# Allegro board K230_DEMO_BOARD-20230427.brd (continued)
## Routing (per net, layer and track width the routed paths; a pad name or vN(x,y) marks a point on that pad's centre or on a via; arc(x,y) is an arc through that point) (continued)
MMC1_D0: length 64.6
  TOP w0.127: v1(31.37,102.49) 27.81,102.49 27.43,102.11 25.78,102.11 24.89,101.22 24.89,99.57 R123.1 ; U4.7 67.62,83.89 v1(68.33,83.19)
  ART06 w0.127: v1(68.33,83.19) 69.09,83.95 69.09,89.28 66.1,92.27 62.8,92.27 61.79,93.28 60.52,93.28 59.05,94.74 51.94,94.74 46.48,100.2 34.54,100.2 32.89,101.85 32,101.85 v1(31.37,102.49)
  BOTTOM w0.127: R189.2 v1(68.33,83.19) 67.82,83.69 U23.2
MMC1_D1: length 66.7
  TOP w0.127: v1(68.33,81.92) 67.45,82.79 U4.8 ; v1(32.64,101.35) 32.13,100.84 29.59,100.84 R124.1
  ART06 w0.127: v1(32.64,101.35) 32.77,101.35 34.29,99.82 46.23,99.82 51.44,94.61 51.44,93.92 51.69,93.66 52.66,93.66 52.81,93.81 52.81,94.09 52.96,94.23 53.17,94.23 53.32,94.09 53.32,93.81 53.47,93.66 53.68,93.66 53.83,93.81 53.83,94.09 53.98,94.23 54.19,94.23 54.34,94.09 54.34,93.81 54.49,93.66 54.7,93.66 54.84,93.81 54.84,94.09 54.99,94.23 55.2,94.23 55.35,94.09 55.35,93.81 55.5,93.66 55.71,93.66 55.86,93.81 55.86,94.09 56.01,94.23 56.22,94.23 56.37,94.09 56.37,93.81 56.52,93.66 57.85,93.66 58.17,93.34 58.38,93.34 59,93.96 59.21,93.96 59.35,93.81 59.35,93.6 58.74,92.98 58.74,92.77 59.6,91.91 64.75,91.91 64.9,91.76 64.9,91.46 65.04,91.31 65.25,91.31 65.4,91.46 65.4,91.76 65.55,91.91 65.83,91.91 68.71,89.03 68.71,84.84 67.82,83.95 67.82,82.42 v1(68.33,81.92)
  BOTTOM w0.127: R190.2 v1(68.33,81.92) 67.82,81.41 U23.3
MMC1_D2: length 66.5
  TOP w0.127: R125.1 25.91,99.44 25.91,100.84 26.16,101.09 27.56,101.09 28.45,101.98 32,101.98 v1(32.51,102.49) ; v1(68.46,90.81) 68.13,90.49 U4.1
  ART06 w0.127: v1(68.46,90.81) 66.56,92.71 62.87,92.71 61.98,93.6 60.96,93.6 58.29,96.27 52.45,96.27 48.13,100.58 46.24,100.58 46.09,100.73 46.09,101.07 45.95,101.22 45.73,101.22 45.59,101.07 45.59,100.73 45.44,100.58 45.23,100.58 45.08,100.73 45.08,101.07 44.93,101.22 44.72,101.22 44.57,101.07 44.57,100.73 44.42,100.58 44.14,100.58 43.99,100.73 43.99,101.07 43.85,101.22 43.63,101.22 43.49,101.07 43.49,100.73 43.34,100.58 43.13,100.58 42.98,100.73 42.98,101.07 42.83,101.22 42.62,101.22 42.47,101.07 42.47,100.73 42.32,100.58 42.11,100.58 41.96,100.73 41.96,101.07 41.81,101.22 41.6,101.22 41.45,101.07 41.45,100.73 41.31,100.58 41.09,100.58 40.95,100.73 40.95,101.07 40.8,101.22 40.59,101.22 40.44,101.07 40.44,100.73 40.29,100.58 40.08,100.58 39.93,100.73 39.93,101.07 39.78,101.22 39.57,101.22 39.42,101.07 39.42,100.73 39.27,100.58 39.06,100.58 38.91,100.73 38.91,101.07 38.77,101.22 38.55,101.22 38.41,101.07 38.41,100.73 38.26,100.58 38.05,100.58 37.9,100.73 37.9,101.07 37.75,101.22 37.54,101.22 37.39,101.07 37.39,100.73 37.24,100.58 37.03,100.58 36.88,100.73 36.88,101.07 36.73,101.22 36.52,101.22 36.37,101.07 36.37,100.73 36.23,100.58 36.01,100.58 35.87,100.73 35.87,101.32 35.72,101.47 35.51,101.47 35.36,101.32 35.36,100.73 35.22,100.6 34.79,100.6 32.89,102.49 v1(32.51,102.49)
  BOTTOM w0.127: U24.2 67.96,91.31 v1(68.46,90.81) R191.2
MMC1_D3: length 66.1
  TOP w0.127: U4.2 67.33,89.39 v1(67.82,88.9) ; v1(31.37,101.35) 28.96,101.35 R126.1
  ART06 w0.127: v1(67.82,88.9) 67.08,89.64 66.87,89.64 66.44,89.22 66.23,89.22 66.08,89.37 66.08,89.58 66.51,90 66.51,90.21 66.04,90.68 64.26,90.68 63.37,91.57 59.44,91.57 57.78,93.22 50.8,93.22 50.51,93.51 50.51,93.72 51,94.21 51,94.42 50.85,94.57 50.64,94.57 50.15,94.08 49.94,94.08 49.79,94.23 49.79,94.44 50.28,94.93 50.28,95.14 50.13,95.29 49.92,95.29 49.43,94.8 49.22,94.8 49.07,94.95 49.07,95.16 49.56,95.64 49.56,95.85 49.41,96 49.2,96 48.71,95.52 48.5,95.52 48.35,95.66 48.35,95.88 48.84,96.36 48.84,96.57 48.69,96.72 48.48,96.72 47.99,96.23 47.78,96.23 47.63,96.38 47.63,96.59 48.12,97.08 48.12,97.29 47.97,97.44 47.76,97.44 47.27,96.95 47.06,96.95 46.92,97.1 46.92,97.31 47.4,97.8 47.4,98.01 47.25,98.16 47.04,98.16 46.56,97.67 46.35,97.67 46.2,97.82 46.2,98.03 46.68,98.52 46.68,98.73 46.54,98.88 46.33,98.88 45.84,98.39 45.63,98.39 45.48,98.54 45.48,98.75 45.79,99.06 45.79,99.24 45.61,99.42 45.43,99.42 45.12,99.11 44.91,99.11 44.58,99.44 34.16,99.44 32.89,100.71 32,100.71 v1(31.37,101.35)
  BOTTOM w0.127: U24.3 67.69,89.03 v1(67.82,88.9) R193.2
NC_NC: length 3.3
  TOP w0.127: R207.2 1.91,38.1
OSPI_CLK: length 43.2
  TOP w0.127: v3(29.79,94.61) 29.72,94.54 29.72,92.25 28.9,91.43 U1.K1 ; J9.14 28.89,106.36 29.46,106.93 32.26,106.93 32.64,107.31 v1(32.64,113.67)
  ART06 w0.127: v3(29.79,94.61) 29.22,95.19 29.22,96.41 29.95,97.13 29.95,109.07 30.61,109.73 30.61,113.28 30.99,113.67 v1(32.64,113.67)
OSPI_CS: length 43.9
  TOP w0.127: J9.6 23.18,118.3 25.65,115.82 25.65,111.38 26.29,110.74 27.18,110.74 v1(27.69,111.25) ; U1.J5 v2(29.22,83.26)
  ART06 w0.076: 28.24,85.6 28.24,84.24 v2(29.22,83.26)
  ART06 w0.127: v1(27.69,111.25) 27.69,108.97 28,108.65 28,98.36 27.18,97.54 27.18,88.37 28.3,87.25 28.3,86.44 28.24,86.39 28.24,85.6
OSPI_D0: length 43.3
  TOP w0.076: U1.K2 29.23,85.86 29.23,86.49
  TOP w0.127: v1(30.86,96.01) 30.35,95.5 30.35,92.44 29.23,91.32 29.23,86.49 ; v1(32,107.57) 29.08,107.57 26.99,105.47 J9.13
  ART06 w0.127: v1(30.86,96.01) 30.77,96.1 30.77,102.91 30.92,103.06 34.27,103.06 34.42,103.21 34.42,103.42 34.27,103.57 30.92,103.57 30.77,103.72 30.77,103.93 30.92,104.08 33.38,104.08 33.53,104.23 33.53,104.44 33.38,104.59 30.92,104.59 30.77,104.74 30.77,105.03 30.9,105.16 31.88,105.16 32,105.28 v1(32,107.57)
OSPI_D1: length 43.4
  TOP w0.127: J9.7 21.27,119.57 25.27,115.57 25.27,111.12 26.04,110.36 v1(28.19,110.36) ; U1.K4 v2(29.22,84.56)
  ART06 w0.076: v2(29.22,84.56) 28.98,84.56 28.7,84.84 28.7,85.98 28.83,86.11
  ART06 w0.127: 28.83,86.11 28.91,86.18 28.91,87.68 27.93,88.66 27.93,97.14 28.74,97.96 28.74,109.82 v1(28.19,110.36)
OSPI_D2: length 43.1
  TOP w0.127: U1.K5 v2(29.22,83.91) ; v1(28.19,109.35) 26.54,109.35 26.17,108.97 25.96,108.97 25.53,109.4 25.32,109.4 25.17,109.25 25.17,109.04 25.6,108.61 25.6,108.4 25.45,108.25 25.24,108.25 24.81,108.68 24.6,108.68 24.45,108.53 24.45,108.32 24.88,107.89 24.88,107.68 24.73,107.53 24.52,107.53 24.09,107.96 23.88,107.96 23.73,107.81 23.73,107.6 24.16,107.17 24.16,106.96 24,106.81 20.83,106.81 19.37,105.35 J9.9
  ART06 w0.076: 28.57,86.36 28.57,86.23 28.49,86.14 28.49,84.65 v2(29.22,83.91)
  ART06 w0.127: v1(28.19,109.35) 28.36,109.18 28.36,98.21 27.56,97.41 27.56,88.52 28.57,87.5 28.57,86.36
OSPI_D3: length 43
  TOP w0.127: v1(29.21,118.36) 28.89,118.68 J9.3 ; v1(28.71,94.61) 28.71,92.62 28.25,92.16 U1.L1
  ART06 w0.127: v1(29.21,118.36) 29.72,118.36 29.97,118.11 29.97,113.79 29.82,113.64 28.98,113.64 28.83,113.49 28.83,113.28 28.98,113.14 29.82,113.14 29.97,112.99 29.97,112.78 29.82,112.63 28.98,112.63 28.83,112.48 28.83,112.27 28.98,112.12 29.82,112.12 29.97,111.97 29.97,111.76 29.82,111.61 28.98,111.61 28.83,111.46 28.83,111.25 28.98,111.1 29.82,111.1 29.97,110.95 29.97,110.11 29.44,109.58 29.44,97.51 28.71,96.79 v1(28.71,94.61)
OSPI_D4: length 43.1
  TOP w0.076: 28.58,86.61 28.58,85.86 U1.L2
  TOP w0.127: J9.12 25.08,105.35 28.57,108.84 v1(32,108.84) ; v1(29.84,96.01) 29.21,95.38 29.21,92.71 28.58,92.08 28.58,86.61
  ART06 w0.127: v1(29.84,96.01) 30.45,96.62 30.45,108.81 31.24,109.6 31.24,112.9 31.37,113.03 31.88,113.03 32,112.9 v1(32,108.84)
OSPI_D5: length 43
  TOP w0.127: J9.5 25.08,120.62 25.23,120.48 25.76,120.48 25.91,120.33 25.91,120.12 25.76,119.97 25.23,119.97 25.08,119.82 25.08,119.61 25.23,119.46 25.76,119.46 25.91,119.31 25.91,119.1 25.76,118.95 25.23,118.95 25.08,118.8 25.08,118.59 25.23,118.44 25.76,118.44 25.91,118.3 25.91,118.08 25.76,117.94 25.23,117.94 25.08,117.79 25.08,117.03 26.16,115.95 26.16,111.76 v1(26.67,111.25) ; U1.L3 v2(27.93,85.21)
  ART06 w0.127: v2(27.93,85.21) 27.93,87.01 26.8,88.14 26.8,97.66 27.65,98.51 27.65,108.5 26.67,109.47 v1(26.67,111.25)
OSPI_D6: length 43.2
  TOP w0.127: U1.L4 v2(27.93,84.56) ; v1(26.35,108.2) 24.45,106.3 23.54,106.3 23.39,106.15 23.39,105.81 23.24,105.66 23.03,105.66 22.88,105.81 22.88,106.15 22.74,106.3 22.53,106.3 22.38,106.15 22.38,105.81 22.23,105.66 22.02,105.66 21.87,105.81 21.87,106.15 21.72,106.3 21.46,106.3 21.27,106.11 J9.10
  ART06 w0.076: v2(27.93,84.56) 27.93,84.72 27.6,85.05 27.6,85.47
  ART06 w0.127: v1(26.35,108.2) 27.05,108.2 27.28,107.98 27.28,107.77 27.13,107.62 26.31,107.62 26.16,107.47 26.16,107.26 26.31,107.11 27.13,107.11 27.28,106.96 27.28,106.75 27.13,106.61 26.31,106.61 26.16,106.46 26.16,106.25 26.31,106.1 27.13,106.1 27.28,105.95 27.28,105.74 27.13,105.59 26.31,105.59 26.16,105.44 26.16,105.23 26.31,105.08 27.13,105.08 27.28,104.93 27.28,104.72 27.13,104.57 26.31,104.57 26.16,104.42 26.16,104.21 26.31,104.07 27.13,104.07 27.28,103.92 27.28,98.78 26.41,97.91 26.41,87.93 27.6,86.74 27.6,85.47
OSPI_D7: length 43.1
  TOP w0.127: v1(26.99,112.65) J9.4 ; U1.L5 v2(27.93,83.91)
  ART06 w0.076: 27.3,85.34 27.3,84.99 27.6,84.7 27.6,84.34 27.93,84.01 v2(27.93,83.91)
  ART06 w0.127: 27.3,85.34 27.3,86.49 26.01,87.78 26.01,98.02 26.92,98.93 26.92,103.5 26.8,103.63 25.91,103.63 25.78,103.76 25.78,113.16 26.04,113.41 26.8,113.41 26.99,113.22 v1(26.99,112.65)
OSPI_DQS: length 43.2
  TOP w0.127: U1.L6 v2(27.93,83.26) ; J9.11 v1(23.18,99.82)
  ART06 w0.076: 26.94,85.58 26.94,84.44 27.14,84.24 27.39,84.24 27.59,84.04 27.59,83.6 v2(27.93,83.26)
  ART06 w0.127: 26.94,85.58 26.94,86.36 25.69,87.61 25.69,96.62 25.46,96.84 22.39,96.84 22.25,96.99 22.25,97.2 22.39,97.35 25.54,97.35 25.66,97.48 25.66,97.66 25.46,97.86 22.39,97.86 22.25,98.01 22.25,98.22 22.39,98.36 25.56,98.36 25.69,98.49 25.69,98.9 25.53,99.06 22.35,99.06 22.23,99.19 22.23,101.6 22.35,101.73 22.86,101.73 22.99,101.6 22.99,100.01 v1(23.18,99.82)
PG_CORE: length 57.3
  TOP w0.254: U17.7 33.63,19.44 v1(33.15,18.95) ; U21.7 33.63,9.91 v1(33.15,9.42) ; v1(38.61,43.31) 38.86,43.05 47.75,43.05 49.15,44.45 R151.2 49.91,45.85 49.91,48.77 50.55,49.41 U20.2
  ART06 w0.254: v1(33.15,9.42) 33.02,9.55 33.02,18.82 v1(33.15,18.95) 33.02,19.08 33.02,25.27 34.04,26.29 34.04,41.15 34.37,41.48 37.41,41.48 37.72,41.78 37.72,42.42 v1(38.61,43.31)
PW_EN: length 119.3
  TOP w0.254: v1(50.06,52.58) 50.55,52.09 U20.7 ; U27.4 64.64,50.93 v1(64.77,50.8) ; v1(54.74,27.3) 54.6,27.44 U28.4 ; v1(42.29,44.96) 41.64,45.61 U12.4
  TOP w0.381: U18.1 57.03,73.92 v1(56.39,73.28)
  ART06 w0.254: v1(42.29,44.96) 43.05,45.72 43.05,48.26 47.37,52.58 v1(50.06,52.58) 50.19,52.7 56.26,52.7 57.99,50.98 64.59,50.98 v1(64.77,50.8) 64.14,50.16 64.14,46.86 58.17,40.89 58.17,30.73 v1(54.74,27.3) 54.61,27.18 54.61,22.1 48.9,16.38 v1(48.9,7.62)
  BOTTOM w0.254: 52.7,1.91 50.16,1.91 48.9,3.17 v1(48.9,7.62) 48.9,7.87 C268.1 ; v1(50.06,52.58) 52.58,52.58 53.85,53.85 53.85,70.74 v1(56.39,73.28)
PWIN_FLASH: length 48.8
  TOP w0.127: J9.8 19.37,120.78 24.77,115.38 24.77,111 25.91,109.86 28.83,109.86 v1(29.34,110.36) ; U1.K7 v2(29.22,81.96)
  ART06 w0.127: v1(29.34,110.36) 29.08,110.11 29.08,97.66 28.22,96.8 28.22,92.91 v2(28.32,92.81)
  BOTTOM w0.127: v2(28.32,92.81) 27.81,92.3 27.81,86.49 27.94,86.36 C27.1 28.32,82.86 v2(29.22,81.96)
RTC_1V8: length 117.6
  TOP w0.254: U1.F15 v2(31.82,77.41) U1.F14
  TOP w0.305: v1(48.77,73.63) Y2.4
  TOP w0.381: v1(71.25,34.67) R150.2 69.61,37.08 64.39,37.08 59.82,41.66 46.86,41.66 45.85,40.64 ; R262.2 v1(71.25,26.8) ; 33.02,1.91 34.29,3.17 56.52,3.17 57.78,1.91 60.33,1.91 61.47,3.05 64.26,3.05 65.41,1.91
  ART06 w0.381: 65.41,1.91 66.67,3.17 68.45,3.17 70.61,5.33 70.61,26.16 v1(71.25,26.8) v1(71.25,34.67)
  BOTTOM w0.381: R62.2 51.44,3.94 52.2,3.17 56.52,3.17 57.78,1.91 60.33,1.91
  vias: v1(43.18,40.39) v1(44.32,40.39)
RTC_1V8_TI: length 42.8
  TOP w0.305: R185.2 42.93,35.18
  ART06 w0.305: v1(45.72,7.75) 45.97,8 45.97,33.02 45.34,33.66 44.07,33.66 v1(43.43,34.29)
  BOTTOM w0.305: 35.56,1.91 36.83,3.17 36.83,4.83 37.85,5.84 43.81,5.84 v1(45.72,7.75)
RTC_CLK_IN: length 20
  TOP w0.076: U1.B12 34.42,79.36 34.92,79.36
  TOP w0.127: R7.2 46.99,70.1 46.74,70.36 46.74,73.66 45.72,74.68 40.44,74.68 39.37,75.74 39.37,77.13 38.3,78.19 37.81,78.19 36.64,79.36 34.92,79.36
RTC_CLK_OUT: length 19.8
  TOP w0.127: 47.37,68.83 46.23,69.98 46.23,73.41 45.47,74.17 40.22,74.17 38.98,75.41 38.98,77.1 38.14,77.94 37.69,77.94 36.6,79.04 U1.A12
RTC_INT0: length 102.3
  TOP w0.102: v2(33.77,81.31) 33.77,80.66 U1.C10
  ART06 w0.127: v1(69.22,11.3) 69.6,11.68 69.6,39.24 69.98,39.62 69.98,43.43 70.99,44.45 70.99,55.58 69.79,56.78 69.79,59.5 68.71,60.58 65.28,60.58 63.5,62.36 63.5,65.91 59.69,69.72 56.77,69.72 55.12,71.37 55.12,75.01 52.4,77.72 50.42,77.72 48.26,79.88 42.29,79.88 40.89,81.28 40.03,81.28 39.81,81.06 34.02,81.06 v2(33.77,81.31)
  BOTTOM w0.127: 67.69,10.03 68.07,10.41 TVS1.1 68.83,10.92 v1(69.22,11.3)
RTC_INT1: length 98.3
  TOP w0.076: U1.B10 34.42,80.66 35.05,80.66
  TOP w0.127: v3(45.59,77.09) 44.96,76.45 41.33,76.45 41.2,76.58 41.2,77.17 39.5,78.87 39.5,79.2 38.76,79.93 37.54,79.93 36.81,80.66 35.05,80.66
  ART06 w0.127: v3(45.59,77.09) 46.1,77.6 46.74,77.6 48.26,76.07 48.26,72.77 50.04,70.99 50.04,68.58 51.44,67.18 54.99,67.18 60.33,61.85 60.33,53.59 60.96,52.96 65.91,52.96 67.13,51.74 67.13,44.65 65.91,43.43 65.91,11.94 v1(66.67,11.18)
  BOTTOM w0.127: v1(66.67,11.18) 66.55,11.05 TVS2.1 65.79,10.41 65.41,10.03
RTC_INT2: length 98
  TOP w0.127: v3(46.61,77.09) 45.97,76.45 45.47,76.45 45.09,76.07 41.15,76.07 40.89,76.33 40.89,76.96 39.15,78.7 39.15,79.08 38.68,79.55 37.55,79.55 36.77,80.34 U1.A10
  ART06 w0.127: v3(46.61,77.09) 47.88,75.82 47.88,72.52 49.66,70.74 49.66,68.45 51.31,66.8 54.86,66.8 59.94,61.72 59.94,53.47 60.77,52.64 65.72,52.64 66.8,51.56 66.8,45.09 65.41,43.69 65.41,20.57 64.77,19.94 64.77,11.81 v1(65.41,11.18)
  BOTTOM w0.127: v1(65.41,11.18) 64.64,10.41 TVS6.1 63.25,10.41 62.87,10.03
RTC_INT3: length 98
  TOP w0.127: v3(45.59,75.69) 45.09,75.18 40.65,75.18 39.79,76.05 39.79,77.15 38.46,78.49 37.88,78.49 36.68,79.69 U1.A11
  ART06 w0.127: v1(64.14,11.18) 63.5,11.81 63.5,43.05 66.42,45.97 66.42,51.44 65.51,52.35 60.55,52.35 59.56,53.34 59.56,61.59 54.74,66.42 50.22,66.42 49.28,67.36 49.28,70.61 46.56,73.33 46.56,74.73 v3(45.59,75.69)
  BOTTOM w0.127: v1(64.14,11.18) 62.36,11.18 TVS7.1 60.71,10.41 60.33,10.03
RTC_INT4: length 97.8
  TOP w0.076: 35.69,78.71 33.77,78.71 U1.C12
  TOP w0.127: v1(48.64,67.82) 47.24,67.82 45.72,69.34 45.72,73.15 45.21,73.66 39.92,73.66 38.61,74.97 38.61,77.09 38.07,77.62 37.62,77.62 36.53,78.71 35.69,78.71
  ART06 w0.127: v1(59.05,11.18) 60.33,12.45 60.33,40.77 66.04,46.48 66.04,51.31 65.28,52.07 60.33,52.07 59.18,53.21 59.18,61.47 54.61,66.04 50.04,66.04 48.64,67.44 v1(48.64,67.82)
  BOTTOM w0.127: 57.78,10.03 58.17,10.41 TVS8.1 v1(59.05,11.18)
RTC_INT5: length 99.1
  TOP w0.127: v2(33.12,78.71) 32.8,79.03 U1.D12
  ART06 w0.127: v2(33.12,78.71) 33.62,79.21 39.18,79.21 42.24,76.15 44.5,76.15 46.1,74.55 46.1,73.36 48.13,71.32 48.13,67.31 49.78,65.66 54.48,65.66 58.8,61.34 58.8,53.09 60.13,51.75 65.09,51.75 65.66,51.18 65.66,46.61 59.11,40.06 59.11,29.9 58.36,29.15 58.36,17.21 57.78,16.64 v1(57.78,11.05)
  BOTTOM w0.127: v1(57.78,11.05) 57.15,11.05 TVS9.1 55.63,10.41 55.24,10.03
RTC_OUT0: length 101.4
  TOP w0.076: U1.B11 34.42,80.01 34.92,80.01
  TOP w0.127: v3(44.32,75.63) 40.64,75.63 40.11,76.16 40.11,77.27 38.86,78.51 38.86,78.87 38.46,79.27 37.47,79.27 36.73,80.01 34.92,80.01
  ART06 w0.127: v1(56.26,11.18) 56.26,16.51 56.9,17.14 56.9,28.19 58.8,30.1 58.8,40.39 65.28,46.86 65.28,51.05 64.92,51.41 59.08,51.41 57.66,52.83 57.66,61.98 54.32,65.32 49.49,65.32 47.75,67.06 47.75,71.25 45.72,73.28 45.72,74.23 v3(44.32,75.63)
  BOTTOM w0.127: v1(56.26,11.18) 55.37,11.18 54.61,10.41 TVS10.1 53.09,10.41 52.7,10.03 51.44,10.03
RTC_OUT1: length 67.7
  TOP w0.127: U1.C11 v2(33.77,80.01)
  ART06 w0.127: v2(33.77,80.01) 33.81,79.97 40.93,79.97 41.72,79.18 47.69,79.18 50.55,76.33 52.91,76.33 54.36,74.88 54.36,70.03 57.3,67.08 61.32,67.08 62.74,65.66 62.74,61.96 66.03,58.67 66.93,58.67 68.07,57.53 68.07,53.84 69.85,52.06 69.85,47.24 v1(69.98,47.12)
  BOTTOM w0.127: R22.1 75.82,46.86 70.23,46.86 v1(69.98,47.12)
SYS_CLK_IN: length 14.7
  TOP w0.076: U1.B8 34.42,81.96 35.05,81.96
  TOP w0.127: R11.2 46.99,79.88 46.39,79.88 43.97,82.31 39.38,82.31 39.14,82.07 35.84,82.07 35.73,81.96 35.05,81.96
SYS_CLK_OUT: length 13.9
  TOP w0.127: 47.37,78.99 46.99,79.38 46.18,79.38 43.75,81.8 36.46,81.8 36.3,81.64 U1.A8
SYS_ON_OFF: length 28.2
  TOP w0.127: K1.1 72.26,23.15 v1(72.26,20.7)
  ART06 w0.127: v1(72.26,20.7) 71.25,19.68 71.25,5.21 67.94,1.91
SYS_RST: length 83.6
  TOP w0.076: U1.B9 34.42,81.31 35.05,81.31
  TOP w0.127: K2.2 77.47,45.34 76.96,44.83 v1(69.98,44.83) ; v1(46.58,78.41) 46.3,78.41 43.42,81.29 40.01,81.29 39.78,81.06 37.3,81.06 37.05,81.31 35.05,81.31
  ART06 w0.127: v1(69.98,44.83) 69.34,45.47 69.34,51.82 67.56,53.59 67.56,57.28 66.67,58.17 65.79,58.17 62.45,61.51 62.01,61.51 61.59,61.93 61.59,65.79 60.85,66.53 57.13,66.53 53.85,69.81 53.85,74.3 52.96,75.18 52.45,75.18 51.82,75.82 50.29,75.82 47.7,78.41 v1(46.58,78.41)
  BOTTOM w0.127: v1(69.98,44.83) 76.58,44.83 77.85,46.1 R223.1 R22.2 C13.2 78.23,49.4 TVS3.1
SYS_SW: length 55.8
  TOP w0.127: K3.2 v1(73.15,37.44) 72.26,37.44
  ART06 w0.127: v1(73.15,37.44) 71.61,37.44 69.98,35.81 69.98,11.18 69.34,10.54 55.24,10.54 v1(54.61,11.18)
  BOTTOM w0.127: 48.9,10.03 49.28,10.41 TVS11.1 50.93,11.18 v1(54.61,11.18)
TEST_EN: length 14
  TOP w0.127: U1.A9 37,80.99 37.2,80.78 43.21,80.78 46.27,77.72 47.37,77.72
TOUCH_INT: length 17.6
  TOP w0.127: J4.10 7.09,93.41 7.09,93.41 5.78,93.41 2.35,89.98 2.35,84.95 3.61,83.69 6.35,83.69 R182.1
TOUCH_RST: length 18.9
  TOP w0.127: J4.11 7.09,93.91 7.09,93.91 5.56,93.91 1.84,90.2 1.84,84.73 3.39,83.19 R183.1
U_3V3: length 0.9
  BOTTOM w0.305: v1(57.66,98.93) 57.4,99.19 R224.2
U_5V:
  vias: v1(52.83,99.44) v1(52.83,98.17) v1(70.61,106.68) v1(70.61,101.98)
UART0_RXD: length 51.3
  TOP w0.127: R54.2 50.55,124.46 v1(50.55,124.33) ; v1(53.09,117.35) 56.39,117.35 56.67,117.63 U25.6
  ART06 w0.127: v1(53.09,117.35) 52.45,117.98 52.45,122.43 v1(50.55,124.33) 49.91,124.33 49.4,123.83 47.24,123.83 45.78,122.36 42.74,122.36 38.86,118.49 38.86,108.33 v1(38.61,108.08)
  BOTTOM w0.127: R94.2 33.78,99.31 33.78,105.79 36.07,108.08 v1(38.61,108.08)
UART0_RXD_3V3: length 13.9
  TOP w0.127: U26.16 66,112.23 67.18,113.41 v1(67.18,115.06) ; v1(60.83,115.06) 59.94,115.95 59.94,117.38 59.69,117.63 U25.9
  ART06 w0.127: v1(67.18,115.06) v1(60.83,115.06)
UART0_TXD: length 51.8
  TOP w0.127: R53.2 v1(49.15,124.33) ; v1(53.09,118.36) 53.59,117.86 56.13,117.86 56.31,118.03 U25.5 ; R92.2 33.91,100.58 33.91,104.9 35.94,106.93 v1(38.1,106.93)
  ART06 w0.127: v1(53.09,118.36) 53.09,122.81 50.93,124.97 49.78,124.97 v1(49.15,124.33) 46.48,124.33 44.96,122.81 42.55,122.81 38.48,118.75 38.48,110.36 38.1,109.98 v1(38.1,106.93)
UART0_TXD_3V3: length 8.1
  TOP w0.127: U26.17 64.46,113.84 62.1,116.2 61.21,116.2 60.45,116.97 60.45,117.49 59.91,118.03 U25.10
UART3_CTS_FT: length 16.6
  TOP w0.127: U26.40 54.5,108.73 v1(52.72,110.51) ; U16.10 46.55,119.82 v1(46.86,119.51)
  BOTTOM w0.127: v1(46.86,119.51) 50.67,115.7 50.67,112.56 v1(52.72,110.51)
UART3_RTS_FT: length 16.8
  TOP w0.127: U26.41 53.99,108.23 v1(52.72,109.5) ; U16.9 46.19,119.42 46.74,118.87 v1(46.74,117.73)
  BOTTOM w0.127: v1(52.72,109.5) 50.04,112.18 50.04,114.43 v1(46.74,117.73)
UART3_RXD: length 85.9
  TOP w0.127: v1(27.94,116.33) 29.84,118.24 40.39,118.24 42.76,120.62 U16.3
  ART06 w0.127: v1(27.94,116.33) 26.83,116.33 24.64,114.14 24.64,102.36 v1(26.42,100.58)
  BOTTOM w0.127: R117.1 27.69,99.31 v1(26.42,100.58) 26.04,100.97 22.86,100.97 20.32,98.42 20.32,79.43 14.22,73.33 14.22,72.39 11.05,69.22 5.08,69.22 J5.8
UART3_RXD_FT: length 18.5
  TOP w0.127: v1(52.71,112.54) 53.86,111.39 53.86,110.61 54.74,109.73 U26.38 ; v1(47.5,121.79) 46.32,120.62 U16.12
  BOTTOM w0.127: v1(52.71,112.54) 52.71,116.58 v1(47.5,121.79)
UART3_TXD: length 86.9
  TOP w0.127: v1(29.21,116.33) 30.73,117.86 40.51,117.86 42.87,120.22 U16.4
  ART06 w0.127: v1(26.42,99.69) 24.26,101.85 24.26,114.43 26.8,116.97 28.57,116.97 v1(29.21,116.33)
  BOTTOM w0.127: R115.1 26.54,99.57 v1(26.42,99.69) 25.65,100.46 22.99,100.46 20.78,98.25 20.78,79.2 14.61,73.02 14.61,72.26 9.65,67.31 J5.10
UART3_TXD_FT: length 17.9
  TOP w0.127: v1(47.5,120.78) 47.5,120.65 47.06,120.22 U16.11 ; v1(52.71,111.52) 53.34,110.89 53.34,110.49 54.6,109.23 U26.39
  BOTTOM w0.127: v1(52.71,111.52) 52.07,112.16 52.07,115.57 47.5,120.14 v1(47.5,120.78)
USB0_DN: length 63.1
  TOP w0.102: U1.B2 34.42,85.86 35.18,85.86
  TOP w0.14: 35.18,85.86 37.42,88.09 40.22,88.09 40.73,88.61 41.79,88.61 v3(41.91,88.73) ; 71.46,73.53 71.46,72.8 71.73,72.53 J11.B7 ; 71.46,73.53 71.38,73.61 71.07,73.61 70.06,72.6 67.77,72.6 67.63,72.46 ; 71.46,73.53 72.53,73.53 J11.A7 ; 67.63,72.46 67.49,72.6 66.42,72.6 v1(66.17,72.35) ; 67.63,72.46 U32.3
  ART06 w0.14: v1(66.17,72.35) 66.38,72.56 67.07,72.56 67.82,73.31 67.82,78.99 67.04,79.77 67.04,85.15 65.25,86.94 59.49,86.94 58.55,87.88 58.55,89.63 56.65,91.52 45.58,91.52 42.7,88.65 42,88.65 v3(41.91,88.73)
USB0_DP: length 64.1
  TOP w0.14: v3(41.91,87.97) 41.91,88.13 41.77,88.27 40.87,88.27 40.36,87.76 39.84,87.76 39.58,87.5 39.28,87.5 39.02,87.76 38.72,87.76 38.47,87.5 38.16,87.5 37.91,87.76 37.56,87.76 36.64,86.84 36.64,86.53 36.35,86.24 36.04,86.24 35.32,85.52 34.76,85.52 U1.A2 ; J11.A6 73.38,73.03 73.52,73.17 73.52,73.89 73.38,74.03 J11.B6 71.62,74.03 71.54,73.95 70.93,73.95 69.92,72.94 67.77,72.94 67.63,73.08 ; 67.63,73.08 U32.2 ; 67.63,73.08 67.49,72.94 66.59,72.94 v1(66.17,73.36)
  ART06 w0.14: v1(66.17,73.36) 66.17,73.15 66.42,72.9 66.93,72.9 67.48,73.45 67.48,73.95 67.32,74.11 67.12,74.11 66.95,74.27 66.95,74.5 67.12,74.67 67.32,74.67 67.48,74.83 67.48,78.85 66.71,79.63 66.71,85.01 65.11,86.61 59.35,86.61 58.21,87.74 58.21,89.49 56.52,91.19 45.72,91.19 42.84,88.31 42.05,88.31 41.91,88.17 v3(41.91,87.97)
USB0_ID: length 60.8
  TOP w0.127: v1(66.67,75.69) U33.3 67.63,76.58 67.75,76.71 69.98,76.71 71.66,75.03 J11.B5 73.43,75.03 74.3,74.17 74.3,72.77 73.55,72.03 J11.A5 ; U1.D3 v2(33.12,85.21)
  ART06 w0.127: v2(33.12,85.21) 35.16,87.25 43.18,87.25 46.23,90.3 56.01,90.3 56.9,89.41 56.9,87.88 59.3,85.48 64.88,85.48 65.94,84.43 65.94,78.84 66.67,78.11 v1(66.67,75.69)
USB0_OTG_EN: length 113.9
  TOP w0.127: v1(42.67,55.63) 42.67,58.42 45.21,60.96 45.21,64.77 46.99,66.55 63.75,66.55 v1(66.29,69.09) 66.61,69.41 U3.4
  BOTTOM w0.127: J5.1 3.3,76.07 3.3,66.93 3.94,66.29 9.65,66.29 16.51,59.44 16.51,51.56 17.4,50.67 17.4,45.34 19.94,42.8 38.86,42.8 39.24,43.18 39.24,52.2 v1(42.67,55.63) ; R41.1 v1(66.29,69.09)
USB0_OTG_VBUS: length 6.6
  TOP w0.381: v1(71.12,67.56) 71.06,67.5 U3.1
  BOTTOM w0.381: v1(71.12,70.74) v1(71.12,67.56) C17.1
USB0_VBUS: length 15.6
  TOP w0.254: U1.C3 v2(33.77,85.21)
  TOP w0.305: v1(46.61,87.63) 46.74,87.5 47.37,87.5
  ART06 w0.254: v1(46.61,87.63) 45.97,88.27 44.83,88.27 43.03,86.46 35.03,86.46 v2(33.77,85.21)
USB1_DN: length 66.7
  TOP w0.14: 71.33,61.46 71.33,60.8 71.67,60.46 J13.B7 ; 71.33,61.46 J13.A7 ; 71.33,61.46 71.25,61.55 70.93,61.55 69.91,62.57 67.77,62.57 67.63,62.43 ; 67.63,62.43 67.49,62.57 66.38,62.57 66.17,62.36 v1(66.17,62.19) ; 67.63,62.43 U31.3 ; U1.A4 34.76,84.22 37.23,84.22 38.65,85.64 42.72,85.64 42.97,85.89 43.2,85.89 43.33,85.77 43.52,85.77 43.72,85.97 43.72,86.16 43.6,86.29 43.6,86.52 43.86,86.78 44.56,86.78 44.91,86.43 v3(44.91,86.32)
  ART06 w0.14: v3(44.91,86.32) 45.21,86.62 47.22,86.62 48.99,88.39 54.64,88.39 55.24,87.79 55.24,86.35 58.36,83.23 62.95,83.23 64.49,81.69 64.49,77.91 65.16,77.24 65.16,62.9 65.49,62.57 65.99,62.57 66.17,62.39 v1(66.17,62.19)
USB1_DP: length 67.4
  TOP w0.102: 35.19,84.56 34.42,84.56 U1.B4
  TOP w0.14: 67.63,63.05 U31.2 ; 67.63,63.05 67.49,62.91 66.47,62.91 v1(66.17,63.2) ; 67.63,63.05 67.77,62.91 70.05,62.91 71.07,61.88 71.54,61.88 71.62,61.96 J13.B6 73.39,61.96 73.53,61.82 73.53,61.1 73.39,60.96 J13.A6 ; v3(44.91,87.33) 44.7,87.12 43.72,87.12 42.58,85.98 38.51,85.98 37.09,84.56 35.19,84.56
  ART06 w0.14: v1(66.17,63.2) 65.87,62.9 65.63,62.9 65.49,63.04 65.49,77.38 64.83,78.05 64.83,81.83 63.09,83.57 58.5,83.57 55.58,86.49 55.58,87.93 54.78,88.73 48.85,88.73 47.08,86.96 45.09,86.96 44.91,87.13 v3(44.91,87.33)
USB1_ID: length 76.3
  TOP w0.076: 35.31,85.21 34.42,85.21 U1.B3
  TOP w0.127: 74.07,62.96 76.33,65.22 76.33,77.34 74.8,78.87 67.75,78.87 67.63,78.74 U33.2 v1(66.04,77.98) ; 74.07,62.96 J13.B5 ; 74.07,62.96 74.55,62.48 74.55,60.58 73.93,59.96 J13.A5 ; v1(46.61,89.03) 43.94,89.03 41.83,86.92 38.02,86.92 36.31,85.21 35.31,85.21
  ART06 w0.127: v1(66.04,77.98) 65.56,78.46 65.56,83.54 64.64,84.45 59.82,84.45 56.52,87.76 56.52,89.28 55.88,89.92 47.5,89.92 v1(46.61,89.03)
USB1_OTG_EN: length 119.9
  TOP w0.127: U6.4 v1(66.17,59.25) 65.41,60.01 65.41,65.53 64.9,66.04 47.24,66.04 45.72,64.52 45.72,60.71 43.18,58.17 43.18,55.12 v1(42.67,54.61)
  BOTTOM w0.127: v1(66.17,59.25) 67.25,59.25 67.69,59.69 R46.1 ; v1(42.67,54.61) 39.75,51.69 39.75,43.05 38.86,42.16 38.86,41.78 38.61,41.53 19.81,41.53 16.13,45.21 16.13,59.31 9.65,65.79 3.68,65.79 2.92,66.55 2.92,73.91 1.91,74.93
USB1_OTG_VBUS: length 9.8
  TOP w0.381: U6.1 71.06,57.34 v1(71.12,57.28)
  BOTTOM w0.381: v1(71.12,63.63) v1(71.12,58.8) v1(71.12,57.28) 70.1,57.28 69.98,57.4 C21.1
USB1_VBUS: length 14.2
  TOP w0.254: U1.A3 36.63,84.89 38.32,86.58 42,86.58 43.89,88.47 47.19,88.47 47.37,88.65
VCM: length 3.5
  TOP w0.254: U1.F3 v2(31.82,84.56)
  BOTTOM w0.254: v2(31.82,84.56) 30.99,85.4 C150.1 C149.1
VSY0: length 8.3
  TOP w0.127: J3.53 45.76,128.61 47,127.37 49.29,127.37 R52.2 R54.1
VTEST: length 16.6
  TOP w0.127: V-TS.1 46.48,81.53 v1(46.48,80.64) ; U1.D8 v2(33.12,81.96)
  ART06 w0.102: v2(33.12,81.96) 33.45,81.63 34.16,81.63
  ART06 w0.127: v1(46.48,80.64) 42.16,80.64 41.02,81.79 37.08,81.79 36.93,81.63 34.16,81.63
N20962765: length 6
  TOP w0.127: Y2.3 49.05,75.46 48.01,74.42 48.01,71.75 R7.1
N20962780: length 3.6
  TOP w0.254: R5.2 C3.1 49.91,69.22 50.43,69.22 Y1.1
N20962782: length 3.7
  TOP w0.254: R6.1 C4.1 49.96,69.68 50.39,69.68 Y1.2
N20963869: length 9
  TOP w0.127: SW1.3 64.77,34.29 65.02,34.54 68.45,34.54 R13.1
N20963881: length 11.2
  TOP w0.127: R14.1 69.72,35.18 63.12,35.18 62.23,34.29 SW1.4
N20968799: length 2.6
  TOP w0.089: U1.K19 v2(29.22,74.16)
  BOTTOM w0.089: R61.1 28.19,73.15 28.7,73.15 28.9,73.35 28.9,73.84 v2(29.22,74.16)
N20969144: length 2.1
  TOP w0.076: U1.T19 v2(24.68,74.16)
  BOTTOM w0.089: R248.1 24,73.49 v2(24.68,74.16)
N20969162: length 3.4
  TOP w0.076: U1.P18 v2(26.63,74.81)
  BOTTOM w0.089: v2(26.63,74.81) 26.3,74.49 25.72,74.49 25.27,74.04 R249.1
N20974230: length 16.3
  TOP w0.127: U1.D4 v2(33.12,84.56) ; 47.37,86.36 46.48,85.47 v1(46.48,85.22)
  ART06 w0.076: 33.95,84.87 33.44,84.87 v2(33.12,84.56)
  ART06 w0.127: v1(46.48,85.22) 46.23,85.47 44.83,85.47 44.2,86.11 35.41,86.11 34.18,84.87 33.95,84.87
N20974244: length 15.2
  TOP w0.127: U1.C4 v2(33.77,84.56) ; 47.37,85.22 46.88,84.72 45.22,84.72 v1(45.09,84.86)
  ART06 w0.127: v1(45.09,84.86) 44.81,84.86 43.94,85.72 35.57,85.72 34.41,84.56 v2(33.77,84.56)
N20974837: length 1.9
  TOP w0.254: v1(68.96,69.34) 69.02,69.41 U3.3
  BOTTOM w0.254: R40.2 68.71,69.09 v1(68.96,69.34)
N20975021: length 2.1
  TOP w0.254: U6.3 69.28,59.25 v1(68.96,59.56)
  BOTTOM w0.381: v1(68.96,59.56) 68.83,59.69 R45.2
N20990697: length 6.8
  TOP w0.127: R11.1 50.16,84.07 50.16,85.34 Y4.3
N20990724: length 3.3
  TOP w0.254: Y3.3 50.55,80.01 49.78,80.01 C11.1 R10.1
N20990759: length 5.3
  TOP w0.254: R8.1 C8.1 50.04,79.5 52.32,79.5 52.87,78.96 Y3.1
N21006529: length 2.8
  TOP w0.127: U1.U6 v2(24.03,83.26)
  BOTTOM w0.127: v2(24.03,83.26) 24.03,83.92 23.5,84.45 R65.2
N21013358: length 17.2
  TOP w0.076: U1.W14 22.73,78.06 20,78.06
  TOP w0.127: 20,78.06 18.94,78.06 14.29,73.41 8.76,73.41 R77.2
N21013362: length 22.5
  TOP w0.127: v1(10.92,72.77) 9.78,71.63 R79.2 ; U1.U12 v2(24.03,79.36)
  ART06 w0.076: v2(24.03,79.36) 23.88,79.36 23.76,79.48 23.01,79.48 22.54,79.95
  ART06 w0.127: v1(10.92,72.77) 10.92,75.06 11.68,75.82 11.68,77.34 12.32,77.98 13.46,77.98 15.24,79.76 16.26,79.76 16.76,80.26 22.22,80.26 22.54,79.95
N21013366: length 22.4
  TOP w0.127: U1.T13 v2(24.68,78.71)
  ART06 w0.076: v2(24.68,78.71) 24.35,79.03 23.89,79.03 23.66,79.26 22.85,79.26 22.35,79.76
  ART06 w0.127: v1(12.45,77.34) 13.34,77.34 15.37,79.38 16.51,79.38 17.02,79.88 22.23,79.88 22.35,79.76
  BOTTOM w0.127: v1(12.45,77.34) 11.81,77.98 11.81,79.25 9.78,81.28 7.37,81.28 7.11,81.53 R81.2
N21013370: length 18.5
  TOP w0.127: R83.2 8.76,76.71 12.06,76.71 v1(12.57,76.2) ; U1.U13 v2(24.03,78.71)
  ART06 w0.076: v2(24.03,78.71) 23.91,78.71 23.58,79.03 22.73,79.03 22.53,79.24
  ART06 w0.127: v1(12.57,76.2) 12.7,76.2 15.54,79.04 16.69,79.04 17.14,79.5 22.26,79.5 22.53,79.24
N21013374: length 17.3
  TOP w0.127: R85.2 10.67,70.48 13.08,72.9 14.24,72.9 19.08,77.74 U1.Y14
N21013378: length 16.6
  TOP w0.127: v3(15.37,77.22) 14.61,77.98 8.64,77.98 R87.2 ; U1.V13 v2(23.38,78.06)
  ART06 w0.127: v2(23.38,78.06) 23.35,78.03 16.17,78.03 15.37,77.23 v3(15.37,77.22)
N21013382: length 20
  TOP w0.127: U1.T12 v2(24.68,79.36) ; R89.2 v1(11.05,76.2)
  ART06 w0.076: 22.8,80.07 23.18,79.69 24.34,79.69 v2(24.68,79.36)
  ART06 w0.127: 22.8,80.07 22.22,80.64 16.64,80.64 16.08,80.09 15.09,80.09 13.49,78.49 12.19,78.49 11.05,77.34 v1(11.05,76.2)
N21014154: length 18.4
  TOP w0.127: R116.1 9.4,78.36 14.99,78.36 v3(16.13,77.22) ; U1.T14 v2(24.68,78.06)
  ART06 w0.076: 23.04,77.74 24.35,77.74 v2(24.68,78.06)
  ART06 w0.127: v3(16.13,77.22) 16.65,77.74 23.04,77.74
N21014156: length 20.3
  TOP w0.127: R118.1 10.41,69.34 v1(13.46,72.39) ; U1.U15 v2(24.68,77.41)
  ART06 w0.076: 22.98,77.09 24.35,77.09 v2(24.68,77.41)
  ART06 w0.127: 22.98,77.09 18.16,77.09 v1(13.46,72.39)
N21014379: length 16.1
  TOP w0.127: v1(31.88,94.61) 31.37,95.12 31.37,97.03 R92.1 ; U1.J4 v2(29.87,84.56)
  ART06 w0.076: v2(29.87,84.56) 29.87,84.68 29.55,85 29.55,85.81
  ART06 w0.127: v1(31.88,94.61) 31.88,94.36 28.8,91.29 28.8,88.85 29.55,88.1 29.55,85.81
N21014381: length 15.6
  TOP w0.127: U1.J3 v2(29.87,85.21)
  ART06 w0.127: v1(31.88,96.01) 32.38,95.5 32.38,94.23 29.21,91.06 29.21,88.9 29.87,88.24 v2(29.87,85.21)
  BOTTOM w0.127: v1(31.88,96.01) 31.88,96.39 R94.1
N21014383: length 14.5
  TOP w0.076: 29.88,86.49 29.88,85.86 U1.J2
  TOP w0.127: R96.1 33.4,96.77 33.4,95.78 32.73,95.11 32.73,94.02 29.88,91.17 29.88,86.49
N21014385: length 13.3
  TOP w0.127: R98.1 32.38,96.9 32.38,94.1 29.55,91.26 U1.J1
N21014387: length 14.4
  TOP w0.127: U1.H1 30.2,91.1 33.02,93.92 33.02,95 33.53,95.5 34.16,95.5 34.42,95.76 34.42,96.65 R100.1
N21014389: length 19.4
  TOP w0.127: U1.J6 v2(29.87,83.26) ; 47.37,84.07 v1(46.35,84.07)
  ART06 w0.102: 34.16,84.23 32.16,84.23 31.52,83.59 30.2,83.59 v2(29.87,83.26)
  ART06 w0.127: 34.16,84.23 34.58,84.23 35.71,85.37 42.52,85.37 43.56,84.33 44.58,84.33 44.83,84.07 v1(46.35,84.07)
N21014391: length 15.1
  TOP w0.076: U1.H2 30.53,85.86 30.53,86.55
  TOP w0.127: R104.1 36.2,97.28 36.2,96.65 30.53,90.98 30.53,86.55
N21014393: length 16
  TOP w0.127: U1.H3 v2(30.52,85.21)
  ART06 w0.127: v2(30.52,85.21) 30.52,88.35 29.91,88.96 29.91,90.74 33.15,93.98 33.15,95.38 v1(33.91,96.14)
  BOTTOM w0.127: v1(33.91,96.14) 33.91,96.52 34.67,97.28 35.05,97.28 R106.1
N21014395: length 17.5
  TOP w0.127: U1.H4 v2(30.52,84.56)
  ART06 w0.076: 30.86,85.47 30.86,85.09 30.52,84.75 v2(30.52,84.56)
  ART06 w0.127: v1(33.66,94.91) 33.66,93.98 30.23,90.55 30.23,89.15 30.86,88.52 30.86,85.47
  BOTTOM w0.127: v1(33.66,94.91) 34.42,95.67 34.42,96.52 34.67,96.77 35.69,96.77 R108.1
N21014397: length 17.1
  TOP w0.127: U1.H5 v2(29.87,83.91)
  ART06 w0.076: v2(29.87,83.91) 29.55,84.23 29.55,84.68 29.34,84.9 29.02,84.9 28.91,85.01 28.91,85.8 29.02,85.91
  ART06 w0.127: v1(30.86,94.61) 28.45,92.2 28.45,88.77 29.21,88.01 29.21,86.11 29.02,85.91
  BOTTOM w0.127: v1(30.86,94.61) 31.37,95.12 31.37,97.03 R110.1
N21014399: length 16.9
  TOP w0.127: U1.G4 v2(30.53,83.91)
  ART06 w0.076: 30.19,85.89 30.19,84.25 v2(30.53,83.91)
  ART06 w0.127: 30.19,85.89 30.19,88.3 29.59,88.9 29.59,90.95 32.77,94.12 32.77,95.89 v1(32.89,96.01)
  BOTTOM w0.127: v1(32.89,96.01) 32.89,96.27 R112.1
N21014401: length 18.7
  TOP w0.127: U1.G5 v2(31.17,83.91)
  ART06 w0.076: v2(31.17,83.91) 30.85,84.24 30.85,84.77 31.11,85.04 31.11,85.22
  ART06 w0.127: 31.11,85.22 31.11,88.77 30.61,89.28 30.61,90.42 34.54,94.36 34.54,95.81 v1(34.92,96.19)
  BOTTOM w0.127: v1(34.92,96.19) 35.61,96.19 36.79,97.37 37.43,97.37 R114.1
N21015109: length 18.7
  TOP w0.127: v2(27.28,83.26) 27.6,83.58 U1.M5
  ART06 w0.076: 25.67,84.96 25.67,84.19 26.27,83.59 26.95,83.59 v2(27.28,83.26)
  ART06 w0.127: 25.67,84.96 25.67,85.46 23.37,87.76 23.37,95 v3(24.13,95.76)
  BOTTOM w0.127: v3(24.13,95.76) 24.13,96.01 25.08,96.96 25.59,96.96 R115.2
N21015111: length 18.2
  TOP w0.127: U1.M4 v2(27.28,83.91)
  ART06 w0.076: v2(27.28,83.91) 27.08,83.91 26.75,84.24 26.25,84.24 25.95,84.54 25.95,85.09
  ART06 w0.127: v3(24.13,94.49) 24.13,87.63 25.95,85.81 25.95,85.09
  BOTTOM w0.127: v3(24.13,94.49) 24.64,95 24.64,95.89 25.27,96.52 26.29,96.52 R117.2
N21015121: length 17.2
  TOP w0.076: v2(26.63,85.21) 27.28,85.21 U1.M3
  ART06 w0.127: v3(25.15,94.49) 25.15,87.63 26.63,86.15 v2(26.63,85.21)
  BOTTOM w0.127: v3(25.15,94.49) 26.54,94.49 R119.2
N21015123: length 17.3
  TOP w0.127: U1.N4 v2(26.63,84.56)
  ART06 w0.127: v3(25.15,95.76) 24.64,95.25 24.64,87.63 26.26,86 26.26,84.92 v2(26.63,84.56)
  BOTTOM w0.127: v3(25.15,95.76) 26.67,95.76 R120.2
N21015125: length 14
  TOP w0.076: U1.M2 27.93,85.86 27.93,86.61
  TOP w0.127: R121.2 30.1,96.9 29.84,96.9 27.93,94.98 27.93,86.61
N21015127: length 13.2
  TOP w0.076: 27.28,86.61 27.28,85.86 U1.N2
  TOP w0.127: 27.28,86.61 27.28,96.36 R122.2
N21015129: length 13.9
  TOP w0.076: 25.98,86.55 25.98,85.21 U1.P3
  TOP w0.127: 25.98,86.55 25.98,96.2 R123.2
N21015131: length 12
  TOP w0.127: U1.N1 26.95,97.18 R124.2
N21015133: length 12.1
  TOP w0.127: U1.P1 26.3,97.02 R125.2
N21015135: length 12.6
  TOP w0.076: 26.63,86.61 26.63,85.86 U1.P2
  TOP w0.127: 26.63,86.61 26.63,97.83 R126.2
N21015137: length 17.7
  TOP w0.127: U1.P5 25.65,83.59 v2(25.33,83.91)
  ART06 w0.127: v2(25.33,83.91) 24.8,83.91 22.1,86.61 22.1,95.16 v3(22.69,95.76)
  BOTTOM w0.127: R127.2 22.69,96.35 v3(22.69,95.76)
N21015139: length 16.7
  TOP w0.127: U1.P4 25.65,84.24 v2(25.33,84.56)
  ART06 w0.127: v2(25.33,84.56) 22.69,87.19 v3(22.69,94.49)
  BOTTOM w0.127: R128.2 23.37,95.89 23.37,95.16 v3(22.69,94.49)
N21015638: length 68.8
  TOP w0.127: U1.U11 v2(24.03,80.01) ; R91.2 v1(9.02,29.21)
  ART06 w0.076: 22.97,81.79 23.13,81.64 23.52,81.64 23.7,81.46 23.7,80.34 v2(24.03,80.01)
  ART06 w0.127: 22.97,81.79 22.6,82.17 16.13,82.17 15.49,81.53 12.83,81.53 10.29,78.99 10.29,70.84 8.36,68.91 8.36,55.32 9.02,54.66 v1(9.02,29.21)
N21015640: length 17
  TOP w0.076: 20.05,78.71 22.73,78.71 U1.W13
  TOP w0.127: 20.05,78.71 19.15,78.71 14.35,73.91 R93.2
N21015650: length 19.1
  TOP w0.127: R95.2 8.76,74.42 13.21,74.42 v1(13.72,74.93) ; U1.V12 v2(23.38,78.71)
  ART06 w0.127: v1(13.72,74.93) 14.35,75.56 14.35,77.34 15.75,78.74 16.89,78.74 17.27,79.12 22.23,79.12 22.64,78.71 v2(23.38,78.71)
N21015652: length 20.7
  TOP w0.127: U1.V11 v2(23.38,80.01)
  ART06 w0.127: v2(23.38,80.01) 22.36,81.03 16.51,81.03 15.93,80.44 14.66,80.44 v1(13.34,79.12)
  BOTTOM w0.127: R97.2 7.11,83.95 7.24,83.82 9.14,83.82 9.4,83.57 9.4,83.06 v1(13.34,79.12)
N21015654: length 20
  TOP w0.127: U1.V10 v2(23.38,80.66)
  ART06 w0.127: v1(12.32,79.12) 14,80.8 15.77,80.8 16.38,81.41 22.48,81.41 23.23,80.66 v2(23.38,80.66)
  BOTTOM w0.127: v1(12.32,79.12) 12.32,79.38 9.14,82.55 7.37,82.55 7.11,82.8 R99.2
N21015656: length 19.1
  TOP w0.127: U1.V9 v2(23.38,81.31)
  ART06 w0.127: v1(11.18,79.12) 13.21,81.15 15.62,81.15 16.26,81.79 22.61,81.79 23.08,81.31 v2(23.38,81.31)
  BOTTOM w0.127: R101.2 7.11,80.14 8.13,79.12 v1(11.18,79.12)
N21015658: length 74.5
  TOP w0.127: R103.2 v1(9.02,24.13) ; U1.U10 v2(24.03,80.66)
  ART06 w0.076: 23.11,82.3 23.55,82.3 23.7,82.14 23.7,81.84 24.03,81.51 v2(24.03,80.66)
  ART06 w0.127: 23.11,82.3 22.99,82.3 22.73,82.55 16,82.55 15.37,81.92 12.7,81.92 9.98,79.2 9.98,70.94 8.08,69.04 8.08,55.19 8.51,54.76 8.51,24.64 v1(9.02,24.13)
N21015660: length 79.3
  TOP w0.127: R105.2 v1(8.13,22.48) ; U1.T11 v2(24.68,80.01)
  ART06 w0.076: v2(24.68,80.01) 24.35,80.34 24.35,82.84 24.26,82.93 23.88,82.93 23.62,83.19
  ART06 w0.127: 23.62,83.19 23.37,83.44 15.88,83.44 15.11,82.68 12.45,82.68 9.4,79.63 9.4,71.17 7.52,69.29 7.52,54.76 7.75,54.53 7.75,22.86 v1(8.13,22.48)
N21015662: length 80.2
  TOP w0.076: v2(24.03,81.96) 24.03,81.31 U1.U9
  TOP w0.127: R107.2 v1(9.02,19.05)
  ART06 w0.076: v2(24.03,81.96) 24.03,82.15 23.7,82.47 23.7,82.75 23.39,83.06 22.73,83.06
  ART06 w0.127: 22.73,83.06 16,83.06 15.24,82.3 12.57,82.3 9.68,79.4 9.68,71.04 7.8,69.16 7.8,55.04 8.13,54.71 8.13,23.62 9.02,22.73 v1(9.02,19.05)
N21015664: length 74.4
  TOP w0.076: 22.23,79.36 22.73,79.36 U1.W12
  TOP w0.127: 22.23,79.36 18.86,79.36 15.7,76.2 v1(13.72,76.2) ; R109.2 v1(9.02,16.51)
  ART06 w0.127: v1(13.72,76.2) 13.08,75.56 12.45,75.56 11.43,74.55 11.43,71.58 8.64,68.78 8.64,55.45 9.53,54.56 9.53,17.02 v1(9.02,16.51)
N21015666: length 90.1
  TOP w0.127: R111.2 v1(9.02,13.97) ; U1.T10 v2(24.68,80.66)
  ART06 w0.076: v2(24.68,80.66) 25,80.98 25,82.31 24.89,82.42
  ART06 w0.127: v1(9.02,13.97) 6.6,16.38 6.6,53.47 7.24,54.1 7.24,69.42 9.09,71.27 9.09,79.83 12.32,83.06 14.99,83.06 16.26,84.33 23.75,84.33 24.7,83.38 24.7,82.61 24.89,82.42
N21015668: length 78.7
  TOP w0.127: v1(12.7,74.93) 13.34,75.56 15.49,75.56 18.96,79.04 U1.Y12 ; R113.2 v1(9.02,11.43)
  ART06 w0.127: v1(9.02,11.43) 10.67,13.08 10.67,29.46 9.91,30.23 9.91,54.66 8.94,55.63 8.94,68.68 11.94,71.68 11.94,74.17 v1(12.7,74.93)
N21032968: length 2.6
  TOP w0.305: U10.3 21.91,29.53 21.72,29.34 C133.1
N21033005: length 0.8
  TOP w0.305: R147.1 21.84,36.58
N21033021: length 3.4
  TOP w0.305: U10.7 21.26,35.38 R147.2 R146.2
N21033049: length 3.7
  TOP w0.305: U8.4 34.66,30.47 34.16,29.97 C126.1 R139.2
N21033134: length 3.9
  TOP w0.305: R140.1 R138.1 34.16,34.54 35.31,33.4 U8.2
N21033168: length 2.8
  TOP w0.305: R148.1 20.7,29.21 21.26,29.77 U10.2
N21033227: length 3.4
  TOP w0.305: U9.4 13.32,46.72 12.83,46.23 C129.1 R143.2
N21033259: length 3.9
  TOP w0.305: U9.2 13.97,49.66 12.83,50.8 R177.2 R178.1
N21033332: length 4.2
  TOP w0.305: U10.1 20.61,30.14 19.56,29.08 R246.2 C130.1
N21034668: length 0.5
  TOP w0.254: U1.E9 v2(32.47,81.31)
N21049023: length 8.7
  TOP w0.127: J7.1 77.29,130.86 76.07,132.08 R31.2 C157.2
N21049035: length 6.1
  TOP w0.127: 67.94,118.75 67.94,119.76 68.83,120.65 70.61,120.65 71.2,121.23 J7.4
N21049037: length 4.6
  TOP w0.127: C161.2 71.5,130.31 J7.3
N21049039: length 4.2
  TOP w0.127: J7.8 69.2,130.3 67.42,132.08 R33.2
N21049041: length 4.9
  TOP w0.127: J7.7 73.3,121.17 72.52,120.4 71.64,120.4 R34.2
N21049043: length 1
  TOP w0.127: 70.5,118.24 69.49,118.24
N21049045: length 1.1
  TOP w0.127: R33.1 C158.2
N21053090: length 3.4
  TOP w0.305: C163.1 30.48,34.67 29.76,34.67 29.46,34.37 U11.7
N21064344: length 3.3
  TOP w0.305: R36.2 31.75,28.57 29.96,30.37 U11.5
N21069878: length 3.4
  TOP w0.305: U11.8 28.96,35.31 R38.2 R37.2
N21080670: length 2.6
  TOP w0.305: R168.1 28.96,28.32 U11.3
N21090577: length 6.9
  TOP w0.254: U1.F9 v2(31.82,80.66)
  ART06 w0.254: v2(31.82,80.66) 32.23,80.25 32.75,80.25 32.94,80.44 v2(37.52,80.44)
  BOTTOM w0.254: v2(37.52,80.44) 37.59,80.52 FB5.1
N21116221: length 4
  TOP w0.305: R170.2 R149.1 C170.1 36.96,18.03 36.06,18.93 U17.1
N21116429: length 0.7
  TOP w0.305: U17.6 33.28,19.93
N21117359: length 4
  TOP w0.305: U20.1 50.05,49.67 49.15,48.77 C190.1 R174.1 R176.1
N21117469: length 0.7
  TOP w0.305: U20.6 51.05,52.44
N21117960: length 4
  TOP w0.305: R192.2 R169.1 C196.1 36.96,8.51 36.06,9.41 U21.1
N21118160: length 0.7
  TOP w0.305: U21.6 33.28,10.41
N21119930: length 0.8
  TOP w0.305: R155.1 42.93,50.42
N21119979: length 3.9
  TOP w0.305: R157.1 R155.2 41.15,49.78 42.29,48.64 U12.2
N21124782: length 3.4
  TOP w0.305: R158.2 C142.1 12.83,20.57 13.32,21.07 U13.4
N21124810: length 3.9
  TOP w0.305: U13.2 13.97,24.13 12.83,25.27 R136.2 R159.1
N21124907: length 3.4
  TOP w0.305: R144.2 C136.2 12.83,33.02 13.32,33.51 U14.4
N21124957: length 3.9
  TOP w0.305: U14.2 13.97,36.58 12.83,37.72 R161.1 R163.1
N21125022: length 0.9
  TOP w0.305: R165.2 63.5,95
N21125032: length 2.3
  TOP w0.305: U15.4 v1(59.99,96.79) 59.85,96.65 59.05,96.65
  BOTTOM w0.305: v1(59.99,96.79) 60.14,96.65 60.58,96.65
N21125082: length 2.6
  TOP w0.305: 64.14,96.65 63.63,96.65 v1(63.37,96.39) 63.12,96.14 U15.2
  BOTTOM w0.305: v1(63.37,96.39) 63.63,96.65 64.14,96.65
N21140101: length 5.2
  TOP w0.127: 72.26,27.65 K1.2
N21140162: length 4.7
  BOTTOM w0.127: R1.2 67.94,8.76 J1.1
N21140164: length 4.6
  BOTTOM w0.127: R2.2 J1.3
N21140180: length 4.6
  BOTTOM w0.127: R3.2 62.87,4.45
N21140182: length 4.6
  BOTTOM w0.127: R4.2 60.33,4.45
N21140355: length 5.2
  TOP w0.127: 72.26,35.44 K3.1
N21156680: length 5.3
  TOP w0.305: R153.2 39.88,18.8 36.96,18.8 36.32,19.44 U17.2
N21156730: length 5.3
  TOP w0.305: U21.2 36.32,9.91 36.96,9.27 39.88,9.27 R156.2
N21166978: length 2.4
  TOP w0.305: U2.4 41.64,30.1 41.15,29.61 R186.2
N21166999: length 3.9
  TOP w0.305: U2.2 42.29,33.4 41.15,34.54 R185.1 R187.1
N21185456: length 5.1
  TOP w0.254: v1(66.43,106.32) 66.34,106.23 U26.4
  BOTTOM w0.305: FB7.2 C226.1 C225.1 66.3,106.19 v1(66.43,106.32)
N21185461: length 4.5
  TOP w0.254: U26.9 65.28,108.71 v1(66.55,108.71)
  BOTTOM w0.305: C224.1 C223.1 66.19,108.48 66.42,108.71 v1(66.55,108.71) 67.04,108.71 FB8.2
N21191941: length 2.4
  TOP w0.127: R201.2 66.91,111.23 U26.14
N21191953: length 2.1
  TOP w0.254: U26.6 v1(66.43,107.23)
  BOTTOM w0.305: v1(66.43,107.23) 66.32,107.34 R202.2
N21192465: length 3.6
  TOP w0.127: U26.63 63.96,103.09 63.44,102.57 63.44,101.18 R203.2
N21192467: length 3.5
  TOP w0.127: R204.2 62.75,102.5 63.46,103.21 U26.62
N21192469: length 3.8
  TOP w0.127: U26.61 62.96,103.35 61.6,101.99 R205.2
N21250278: length 1.6
  TOP w0.127: R209.2 58.51,116.02 U25.8
N21252465: length 16.5
  TOP w0.076: 33.9,86.61 33.77,86.49 33.77,85.86 U1.C2
  TOP w0.127: 47.37,90.93 46.34,89.9 40.68,89.9 39.78,89.01 37.19,89.01 34.8,86.61 33.9,86.61
N21252472: length 19.3
  TOP w0.076: 33.12,86.49 33.12,85.86 U1.D2
  TOP w0.127: 33.12,86.49 33.12,86.72 33.74,87.34 34.16,87.34 38.65,91.82 39.5,91.82 40.78,90.54 44.7,90.54 47.37,93.22
N21252475: length 14.8
  TOP w0.127: U1.B1 34.75,86.18 37.27,88.71 39.94,88.71 40.78,89.55 47.13,89.55 47.37,89.79
N21252478: length 23
  TOP w0.102: U1.G3 31.17,85.21 v2(31.82,85.21)
  TOP w0.127: v3(38.23,92.58) 39.75,92.58 41.15,91.19 43.69,91.19 46.1,93.6 46.1,94.23 47.37,95.5
  ART06 w0.127: v3(38.23,92.58) 38.23,91.61 v2(31.82,85.21)
N21252481: length 16.6
  TOP w0.127: U1.C1 33.45,86.66 33.8,87.02 34.82,87.02 37.1,89.29 39.61,89.29 40.51,90.2 45.49,90.2 47.37,92.08
N21252484: length 19.4
  TOP w0.127: U1.D1 32.8,86.77 33.69,87.66 34.04,87.66 38.58,92.2 39.62,92.2 40.93,90.9 43.91,90.9 47.37,94.36
N21259407: length 4.6
  BOTTOM w0.127: R15.2 55.24,4.45
N21259420: length 4.6
  BOTTOM w0.127: R12.2 57.78,4.45
N21259441: length 4.6
  BOTTOM w0.127: R16.2 52.7,4.45
N21259446: length 5.1
  BOTTOM w0.127: 50.16,4.45 49.53,5.08 49.53,8.38 R17.2
N21267992: length 2.3
  TOP w0.254: R211.1 59.94,51.44 U27.9
N21270973: length 8.5
  TOP w0.305: R152.2 C176.2 54.36,76.2 55.37,77.22 55.37,80.26 56.9,81.79 57.4,81.79
N21271073: length 5
  TOP w0.254: U18.8 55.4,75.84 C176.1 R152.1 R175.1 R229.1
N21271180: length 2.8
  TOP w0.305: R172.2 56.52,77.72 57.54,76.7 U18.7
N21272323: length 2.3
  TOP w0.254: U28.9 49.78,27.94 R215.1
N21284521: length 2
  TOP w0.381: R230.2 C239.1 R171.1
N21284561: length 1.3
  TOP w0.381: R229.2 R230.1
N21284570: length 1.1
  TOP w0.381: R232.1 R171.2
N21299161: length 5.5
  TOP w0.127: R217.2 66.17,48.26 66.17,50.16 64.9,51.44 U27.5
N21299164: length 4.9
  TOP w0.127: U27.6 65.29,51.94 66.8,50.42 R219.2
N21299301: length 2.1
  TOP w0.254: R220.2 U28.5
N21299304: length 2.4
  TOP w0.254: R233.2 55.24,28.44 U28.6
N21314838: length 9.6
  TOP w0.381: 10.16,1.91 10.16,4.45 14.1,8.38 R222.1
N21326640: length 5
  BOTTOM w0.127: R245.1 65.41,86.36 65.09,86.04 U22.4
N21346225: length 13.1
  TOP w0.127: GPIO25.1 29.21,97.28 28.83,97.28 27.6,96.05 U1.M1
N21347019: length 1.4
  TOP w0.381: R19.2 LED1.1
N21376209: length 0.5
  TOP w0.076: v2(28.9,54.54) 28.57,54.22 U5.J8
N21376277: length 4
  TOP w0.127: 23.11,50.54 23.63,50.54 U5.B3
  TOP w0.381: 23.11,50.54 20.2,50.54 R63.2
N21377535: length 2.7
  TOP w0.127: U30.H5 42.16,113.28 v2(41.27,112.39)
  BOTTOM w0.127: v2(41.27,112.39) 41.02,112.14 R47.2
N21379070: length 2
  TOP w0.076: 45.43,110.53 44.91,110.53 U30.C2
  TOP w0.127: v3(45.72,110.53) 45.43,110.53
  BOTTOM w0.127: C24.1 45.47,110.78 v3(45.72,110.53)
N21380363: length 9.1
  TOP w0.076: R250.1 30.61,72.82 29.87,73.55 29.87,76.11 U1.J16
N21407823: length 5.9
  TOP w0.127: R251.1 33.91,47.24 32.8,48.35 32.8,49.81 U5.R3
N21433380: length 6.3
  TOP w0.127: U30.M6 42.55,115.16 v2(42.55,114.81)
  BOTTOM w0.127: R50.2 39.62,112.78 41.78,112.78 42.55,113.54 v2(42.55,114.81)
N21453086: length 7.3
  TOP w0.127: v1(70.99,81.03) 68.2,81.03 67.54,81.69 U4.9
  BOTTOM w0.127: R55.1 71.25,81.03 v1(70.99,81.03)
N21465198: length 2.2
  TOP w0.127: U1.U7 v2(24.03,82.61)
  BOTTOM w0.127: R56.2 23.32,83.31 v2(24.03,82.61)
N21605373: length 2.9
  TOP w0.381: Q2.1 59.69,21.72
N21605375: length 3.1
  TOP w0.381: Q2.3 64.14,24.64 R137.1 R263.1
N21605461: length 1.7
  TOP w0.381: Q1.1 62.55,26.86 R263.2
N21607257: length 2.7
  TOP w0.127: C155.1 FB6.2 U7.1
N21607310: length 4.7
  TOP w0.127: 63.37,137.08 64.21,137.08 64.77,136.53 TVS14.1 65.53,135.76 C156.1 C270.1
N21610834: length 1.7
  TOP w0.127: U16.8 45.28,118.42 v1(45.47,118.24)
  BOTTOM w0.127: R23.1 v1(45.47,118.24)
N21611781: length 3.8
  TOP w0.305: U29.2 57.15,99.69 v1(57.66,100.2)
  BOTTOM w0.305: v1(57.66,100.2) 55.75,100.2

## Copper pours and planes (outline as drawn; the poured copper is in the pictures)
AVDD_1V8 on TOP: 62.61,92.84 62.61,90.81 62.36,90.55 61.09,90.55 59.56,92.08 59.56,92.96 59.69,93.09 62.36,93.09
AVDD_1V8 on BOTTOM: 32.51,84.58 34.92,84.58 35.18,84.84 35.18,85.6 35.05,85.72 32.77,85.72 32.64,85.6 32.64,85.09 32.38,84.84 32.38,84.71
AVDD_1V8 on BOTTOM: 56.77,81.28 56.77,87.63 60.83,91.69 62.74,91.69 62.99,91.95 62.99,93.34 62.87,93.47 59.69,93.47 54.74,88.52 54.74,81.28 54.99,81.03 56.52,81.03
AVDD_1V8 on ART06: 36.83,82.55 41.53,82.55 42.55,81.53 47.88,81.53 49.02,80.39 55.63,80.39 55.75,80.52 55.75,82.93 55.63,83.06 53.85,83.06 53.21,83.69 43.81,83.69 42.8,84.71 35.94,84.71 34.92,83.69 32.26,83.69 31.5,82.93 31.5,82.3 31.62,82.17 36.45,82.17
AVDD_PLL_0V8 on TOP: 44.7,51.18 45.97,51.18 46.1,51.31 46.1,58.67 45.97,58.8 44.45,58.8 44.32,58.67 44.32,52.7 44.58,52.45 44.58,51.31
AVDD_PLL_0V8 on BOTTOM: 45.47,57.02 45.47,62.61 47.5,64.64 47.5,74.42 47.37,74.55 45.97,74.55 45.85,74.42 45.85,65.28 43.43,62.87 43.43,57.02 43.56,56.9 45.34,56.9
AVSS1 on BOTTOM: 31.62,79.76 31.62,80.14 31.88,80.39 32.77,80.39 33.66,79.5 33.66,78.99 33.53,78.87 33.15,78.87 32.38,79.63 31.75,79.63
GND on TOP: 12.32,47.75 12.19,47.88 12.19,49.4 12.32,49.53 13.34,49.53 13.46,49.4 13.46,48.9 13.59,48.77 16.26,48.77 16.38,48.9 16.38,51.82 16.51,51.94 17.53,51.94 17.65,51.82 17.65,44.58 17.53,44.45 16.51,44.45 16.38,44.58 16.38,47.62 16.26,47.75
GND on TOP: 79.12,101.09 79.12,99.06 78.99,98.93 71.63,98.93 71.5,99.06 71.5,101.09 71.63,101.22 78.99,101.22
GND on TOP: 15.62,28.07 15.49,27.94 12.32,27.94 12.19,28.07 12.19,29.34 12.32,29.46 15.49,29.46 15.62,29.34
GND on TOP: 68.45,96.77 68.58,96.65 68.58,93.6 68.45,93.47 64.77,93.47 64.64,93.6 64.64,96.65 64.77,96.77
GND on TOP: 12.32,34.67 12.19,34.8 12.19,36.32 12.32,36.45 13.34,36.45 13.46,36.32 13.46,35.81 13.59,35.69 16.26,35.69 16.38,35.81 16.38,38.73 16.51,38.86 17.27,38.86 17.4,38.73 17.4,31.5 17.27,31.37 16.51,31.37 16.38,31.5 16.38,34.54 16.26,34.67
GND on TOP: 44.2,83.31 42.67,83.31 42.55,83.44 42.55,84.96 42.67,85.09 44.2,85.09 44.32,84.96 44.32,83.44
GND on TOP: 71.63,19.68 78.49,19.68 78.61,19.56 78.61,17.02 78.49,16.89 71.63,16.89 71.5,17.02 71.5,19.56
GND on TOP: 77.85,94.36 77.72,94.23 74.17,94.23 74.04,94.36 74.04,97.66 74.17,97.79 77.6,97.79 77.85,97.54
GND on TOP: 71.63,11.05 78.36,11.05 78.49,10.92 78.49,8.51 78.36,8.38 71.63,8.38 71.5,8.51 71.5,10.92
GND on TOP: 14.73,40.39 15.62,40.39 15.75,40.51 15.75,43.05 15.62,43.18 14.73,43.18 14.61,43.05 14.61,40.51
GND on TOP: 34.67,64.26 34.54,64.14 32.51,64.14 32.38,64.26 32.38,66.93 32.51,67.06 34.54,67.06 34.67,66.93
GND on TOP: 0.64,110.74 0.64,138 1.03,138.96 2,139.36 15.83,139.36 16.26,138.94 16.26,136.27 8,128.02 8,110.87 7.24,110.11 1.27,110.11
GND on TOP: 62.1,97.16 62.1,95.12 62.61,94.61 62.61,93.47 62.48,93.34 60.71,93.34 60.58,93.47 60.58,94.61 61.09,95.12 61.09,97.66 61.72,98.3 64.01,98.3 64.14,98.17 64.14,97.54 64.01,97.41 62.36,97.41
GND on TOP: 6.86,104.52 6.73,104.39 3.81,104.39 3.68,104.52 3.68,107.7 3.81,107.82 6.73,107.82 6.86,107.7
GND on TOP: 71.63,109.35 74.42,109.35 74.55,109.22 74.55,107.31 74.42,107.19 71.63,107.19 71.5,107.31 71.5,109.22
GND on TOP: 18.29,49.91 20.57,49.91 20.7,49.78 20.7,48.9 20.57,48.77 18.29,48.77 18.16,48.9 18.16,49.78
GND on TOP: 54.86,87.63 54.86,83.19 54.74,83.06 54.1,83.06 53.98,83.19 53.98,85.47 53.85,85.6 52.32,85.6 52.2,85.72 52.2,87.38 52.07,87.5 50.42,87.5 50.29,87.63 50.29,88.14 50.42,88.27 54.23,88.27
GND on TOP: 44.7,46.61 44.58,46.74 41.15,46.74 41.15,49.02 41.78,48.39 41.78,47.88 41.91,47.75 44.58,47.75 44.7,47.88 44.7,50.8 44.83,50.93 45.97,50.93 46.1,50.8 46.1,43.69 45.97,43.56 44.83,43.56 44.7,43.69
GND on TOP: 77.47,79.5 74.17,79.5 74.04,79.63 74.04,81.92 74.17,82.04 77.47,82.04 77.6,81.92 77.6,79.63
GND on TOP: 23.88,64.64 23.75,64.52 21.59,64.52 21.46,64.64 21.46,66.93 21.59,67.06 23.75,67.06 23.88,66.93
GND on TOP: 44.96,78.61 44.96,76.71 44.83,76.58 43.56,76.58 43.43,76.71 43.43,78.11 43.31,78.23 42.42,78.23 42.29,78.36 42.29,80.39 42.42,80.52 43.05,80.52
GND on TOP: 71.37,78.36 74.42,78.36 74.55,78.23 74.55,76.96 73.79,76.2 71.37,76.2 71.25,76.33 71.25,78.23
